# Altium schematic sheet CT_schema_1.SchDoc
size 646 x 258 mm
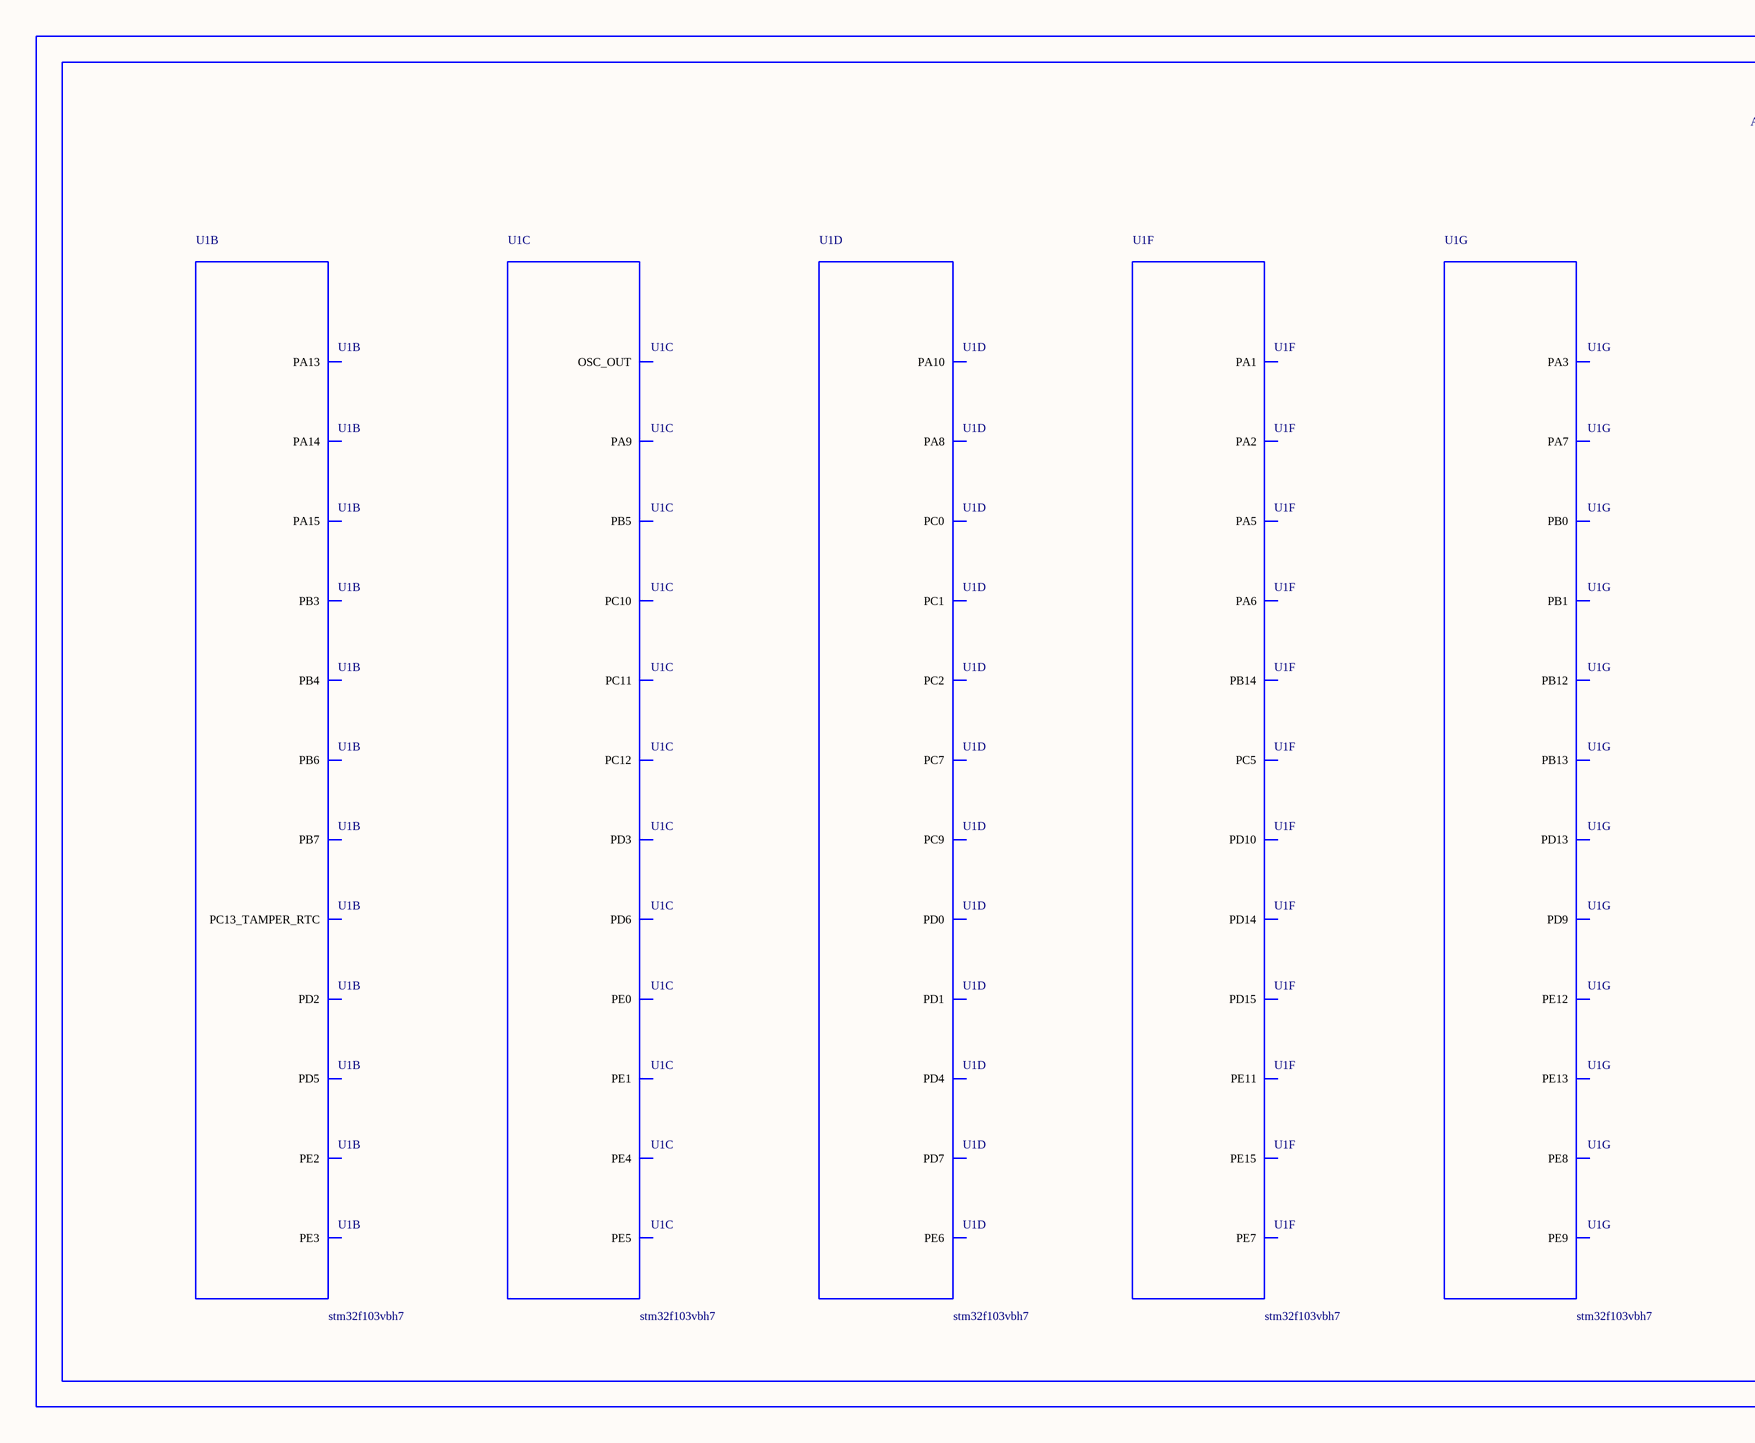
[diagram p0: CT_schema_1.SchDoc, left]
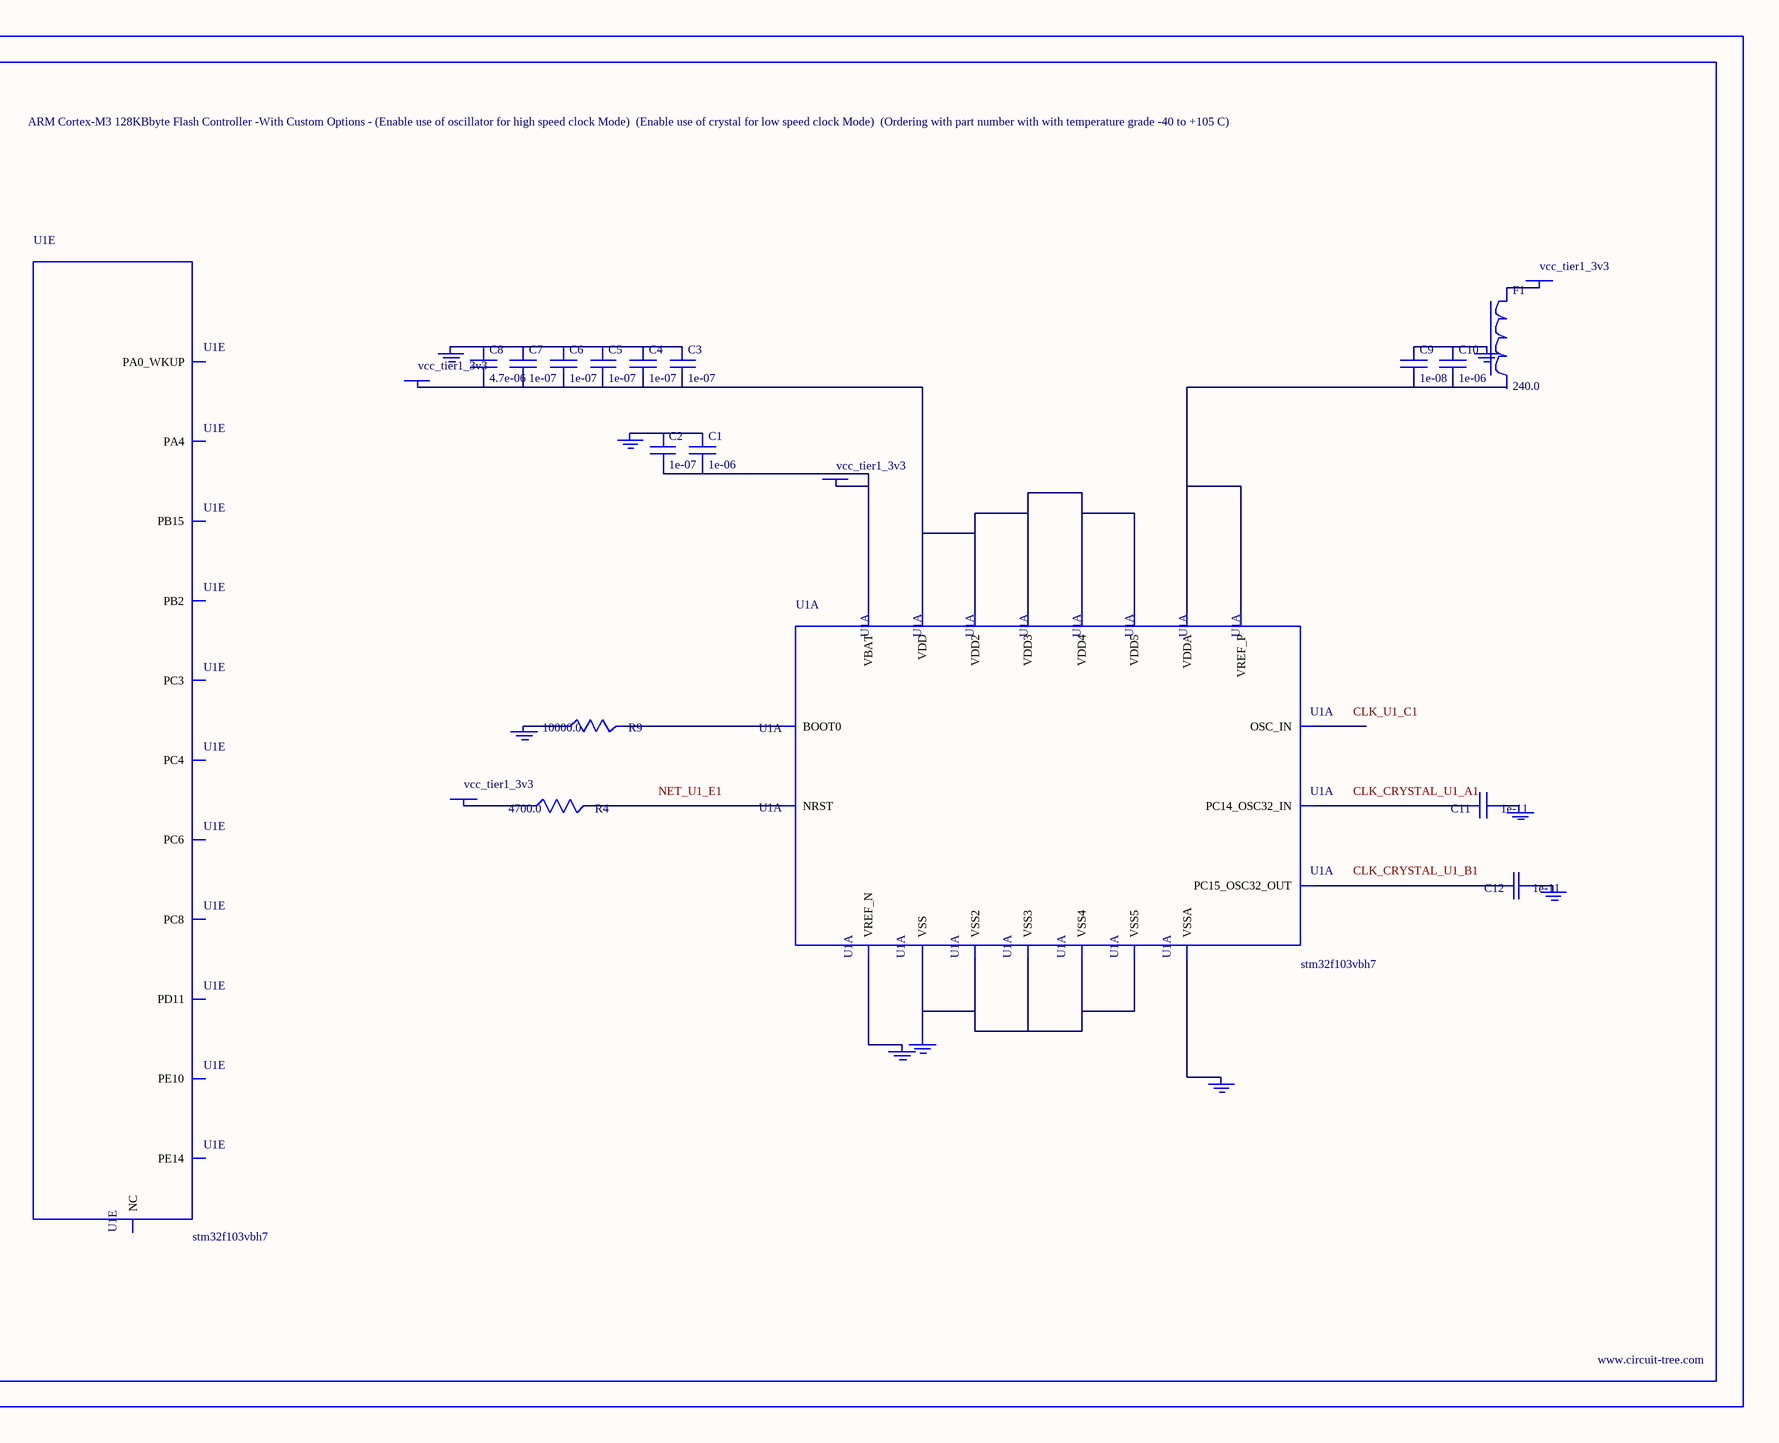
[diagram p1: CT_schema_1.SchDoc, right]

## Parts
BORDER0  (no value)
C1  1e-06  [C0603]
C2  1e-07  [C0603]
C3  1e-07  [C0603]
C4  1e-07  [C0603]
C5  1e-07  [C0603]
C6  1e-07  [C0603]
C7  1e-07  [C0603]
C8  4.7e-06  [C0603]
C9  1e-08  [C0603]
C10  1e-06  [C0603]
C11  1e-11  [C0402]
C12  1e-11  [C0402]
F1  240.0  [L0603]
GND_INSTANCE_0_0  (no value)
GND_INSTANCE_0_1  (no value)
GND_INSTANCE_0_2  (no value)
GND_INSTANCE_0_3  (no value)
GND_INSTANCE_0_4  (no value)
GND_INSTANCE_0_5  (no value)
GND_INSTANCE_0_6  (no value)
GND_INSTANCE_0_7  (no value)
GND_INSTANCE_0_8  (no value)
POWER_INSTANCE_0_0  vcc_tier1_3v3
POWER_INSTANCE_0_1  vcc_tier1_3v3
POWER_INSTANCE_0_2  vcc_tier1_3v3
POWER_INSTANCE_0_3  vcc_tier1_3v3
R4  4700.0  [R0603]
R9  10000.0  [R0603]
U1  stm32f103vbh7  [LFBGA100]  (parts A,B,C,D,E,F,G of 10)

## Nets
NetC1_1: C1.1 C2.1 GND_INSTANCE_0_0.0(GND)
NetC1_2: C1.2 C2.2 POWER_INSTANCE_0_0.0(PWR) U1.B2(VBAT)
NetC3_1: C3.1 C4.1 C5.1 C6.1 C7.1 C8.1 GND_INSTANCE_0_2.0(GND)
NetC3_2: C3.2 C4.2 C5.2 C6.2 C7.2 C8.2 POWER_INSTANCE_0_2.0(PWR) U1.D2(VDD) U1.F4(VDD2) U1.F5(VDD3) U1.F6(VDD4) U1.F7(VDD5)
NetC9_1: C9.1 C10.1 GND_INSTANCE_0_1.0(GND)
NetC9_2: C9.2 C10.2 U1.J1(VREF_P) U1.K1(VDDA)
NetC11_1: C11.1 GND_INSTANCE_0_4.0(GND)
NetC11_2: C11.2 U1.A1(PC14_OSC32_IN)
NetC12_1: C12.1 GND_INSTANCE_0_5.0(GND)
NetC12_2: C12.2 U1.B1(PC15_OSC32_OUT)
NetF1_1: F1.1 POWER_INSTANCE_0_1.0(PWR)
NetGND_INSTANCE_0_3_0: GND_INSTANCE_0_3.0(GND) R9.1
NetGND_INSTANCE_0_6_0: GND_INSTANCE_0_6.0(GND) U1.G1(VSSA)
NetGND_INSTANCE_0_7_0: GND_INSTANCE_0_7.0(GND) U1.H1(VREF_N)
NetGND_INSTANCE_0_8_0: GND_INSTANCE_0_8.0(GND) U1.C2(VSS) U1.E4(VSS2) U1.E5(VSS3) U1.E6(VSS4) U1.E7(VSS5)
NetPOWER_INSTANCE_0_3_0: POWER_INSTANCE_0_3.0(PWR) R4.1
NetR4_2: R4.2 U1.E1(NRST)
NetR9_2: R9.2 U1.D5(BOOT0)

Not connected (* = marked no-connect by the designer): F1 2; U1 A2(PC13_TAMPER_RTC) A3(PE2) A5(PB7) A6(PB4) A7(PB3) A8(PA15) A9(PA14) A10(PA13) B3(PE3) B5(PB6) B6(PD5) B7(PD2) B8(PC11) B9(PC10) C1(OSC_IN) C3(PE4) C4(PE1) C5(PB5) C6(PD6) C7(PD3) C8(PC12) C9(PA9) D1(OSC_OUT) D3(PE5) D4(PE0) D6(PD7) D7(PD4) D8(PD0) D9(PA8) D10(PA10) E2(PC2) E3(PE6) E8(PD1) E9(PC9) E10(PC7) F1(PC0) F2(PC1) F3(PC3) F8(NC) F9(PC8) F10(PC6) G2(PA0_WKUP) G3(PA4) G4(PC4) G5(PB2) G6(PE10) G7(PE14) G8(PB15) G9(PD11) G10(PD15) H2(PA1) H3(PA5) H4(PC5) H5(PE7) H6(PE11) H7(PE15) H8(PB14) H9(PD10) H10(PD14) J2(PA2) J3(PA6) J4(PB0) J5(PE8) J6(PE12) J8(PB13) J9(PD9) J10(PD13) K2(PA3) K3(PA7) K4(PB1) K5(PE9) K6(PE13) K8(PB12)

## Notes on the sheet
- Labels drawn without touching a wire or pin: CLK_CRYSTAL_U1_A1, CLK_CRYSTAL_U1_B1, CLK_U1_C1, NET_U1_E1

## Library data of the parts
BORDER0 = BORDER_PAGE0
C1 C10 = C0603C105K3RACTU
C2-C7 = 06035C104K4Z2A
C8 = GRM188R6YA475KE15D
C9 = 06035C103K4Z2A
C11 C12 = C0402C100K3GACTU
F1 = Z0603C241ASMST
GND_INSTANCE_0_0-GND_INSTANCE_0_8 = GND
POWER_INSTANCE_0_0-POWER_INSTANCE_0_3 = PWR
R4 = RC0603JR-074K7L
R9 = RC0603JR-0710KL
